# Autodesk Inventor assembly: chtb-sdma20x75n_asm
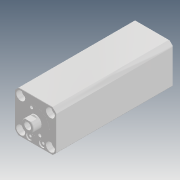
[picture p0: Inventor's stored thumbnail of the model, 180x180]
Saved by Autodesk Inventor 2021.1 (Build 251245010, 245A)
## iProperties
Created: 2018-05
Part Number: chtb-sdma20x75n_asm
Description: STEP AP214
Document SubType Name: Assembly
Designer: user
Title: chtb-sdma20x75n_asm.STEP
Revision Number: ÈÎºÎ
Sending System: SolidWorks 2016
Preprocessor: SwSTEP 2.0
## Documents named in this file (5)
- D:\Vault_2016\Projekty\Clamptek\Hydraulic\CHTB\CHTB-20\Inventor\CHTB-SDMA20x75N\chtb-sdma20x75n_asm.iam
- D:\Vault_2016\Projekty\Clamptek\Hydraulic\CHTB\CHTB-20\Inventor\CHTB-SDMA20x75N\CHTB-SDMA20X75NBT.ipt
- D:\Vault_2016\Projekty\Clamptek\Hydraulic\CHTB\CHTB-20\Inventor\CHTB-SDMA20x75N\CHTB-SDMA20X75NHSG.ipt
- D:\Vault_2016\Projekty\Clamptek\Hydraulic\CHTB\CHTB-20\Inventor\CHTB-SDMA20x75N\QG_3.ipt
- D:\Vault_2016\Projekty\Clamptek\Hydraulic\CHTB\CHTB-20\Inventor\CHTB-SDMA20x75N\socket set screw flat point_iso_ISO 4026 - M5 x 5-N.ipt
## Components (5 placed, 5 different names)
1. CHTB-SDMA20X75NBT_1
2. CHTB-SDMA20X75NHSG_2
3. QG_3_3
4. socket set screw flat point_iso_ISO 4026 - M5 x 5-N_4
5. socket set screw flat point_iso_ISO 4026 - M5 x 5-N_5
